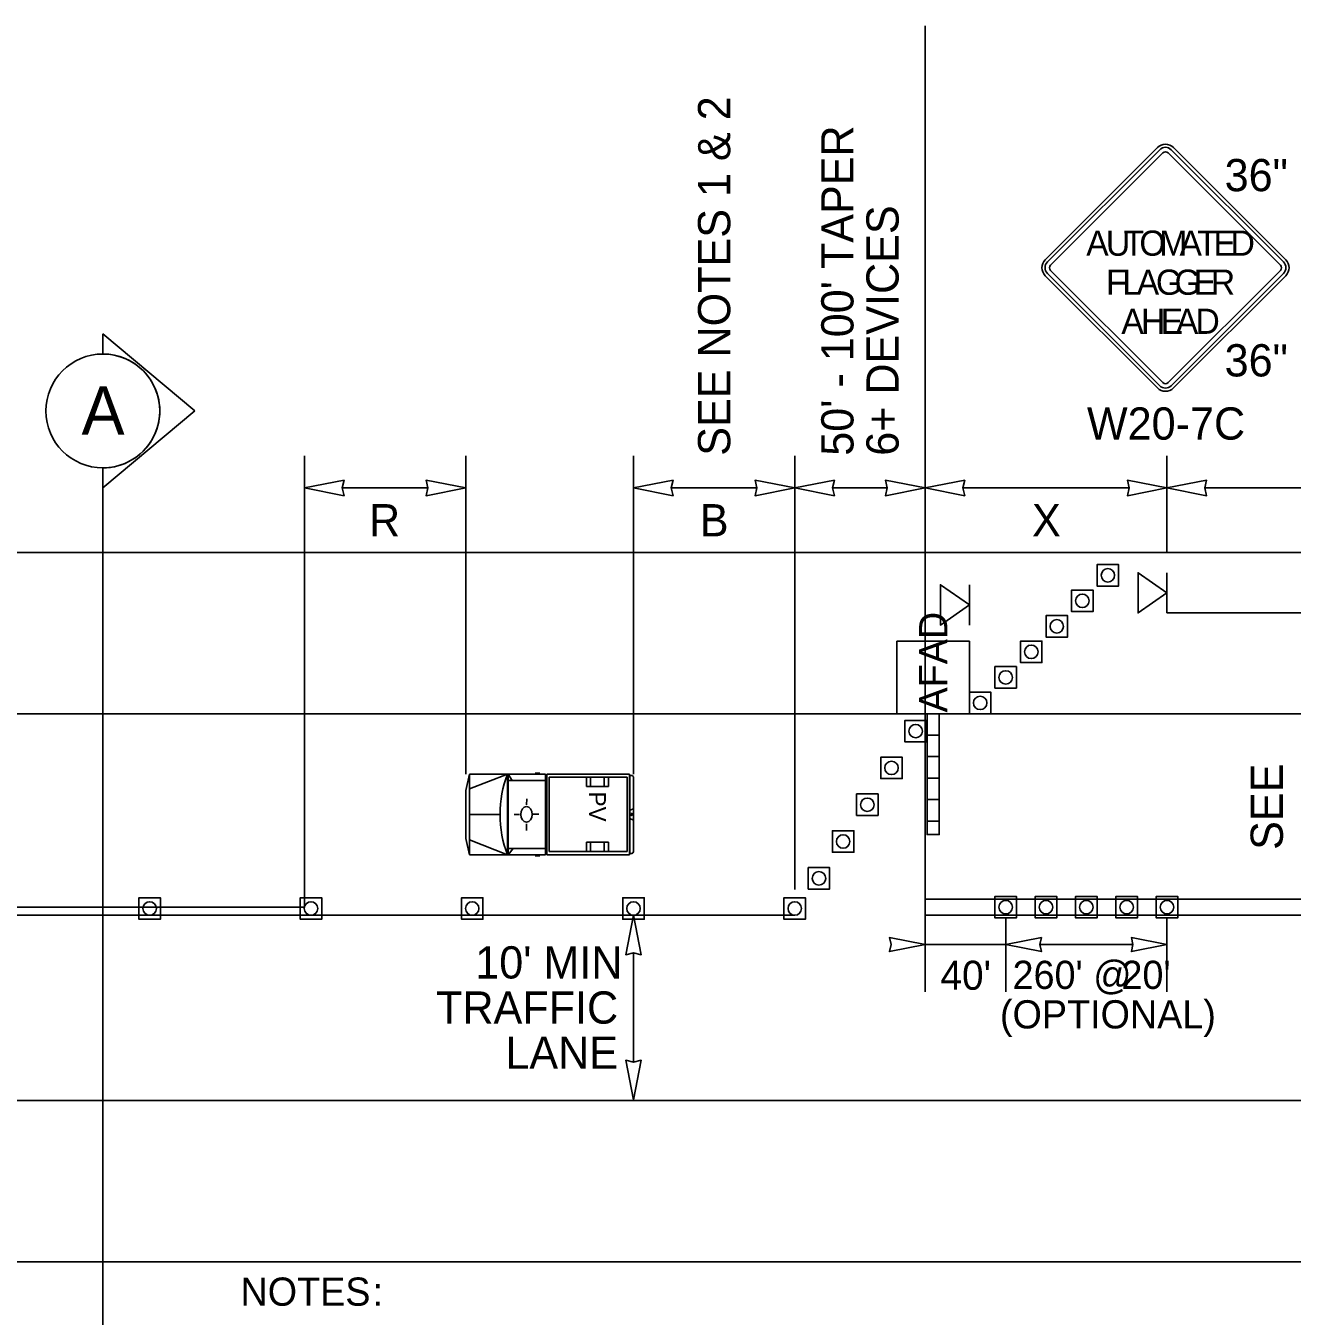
# Model space of a CAD drawing. Extents: x 99999.1 to 100095.7, y 99995 to 100010.7.
# Drawn here: x 100009.243 to 100012.384, y 100005.597 to 100008.799 of the extents above; entities that cross this region are included whole.
import ezdxf

# ---------------------------------------------------------------- set-up
doc = ezdxf.new("R2010")
doc.units = 0
for name, color, linetype in [('RD_ED_ShoulderPavedEdge', 7, 'Continuous'), ('RD_MK_LineDblYellowCenter', 7, 'Continuous'), ('RD_MK_LineEdgeWhite', 7, 'Continuous'), ('RD_MK_LineNoPass', 7, 'Continuous'), ('RD_MK_LineSkipCenter', 7, 'Continuous'), ('SH_GI_GeneralNotesBodyText', 7, 'Continuous'), ('SH_TI_WZSectionCut', 7, 'Continuous'), ('TR_SN_ConstructionSigns', 7, 'Continuous'), ('TR_WZ_AFAD', 7, 'Continuous'), ('TR_WZ_PortableSignMountBlk-Org', 7, 'Continuous'), ('TR_WZ_PortableSignMountBlk-Wht', 7, 'Continuous'), ('TR_WZ_ProtectiveVehicle', 7, 'Continuous'), ('TR_WZ_TrafficCone', 7, 'Continuous'), ('TR_WZ_WorkZoneDetails', 7, 'Continuous'), ('TR_WZ_WorkZoneTextCurrent', 7, 'Continuous')]:
    doc.layers.add(name, color=color, linetype=linetype)

msp = doc.modelspace()

# ---------------------------------------------------------------- linework, layer by layer
at = {"layer": 'RD_ED_ShoulderPavedEdge'}
for p, q in [((100000.1076, 100007.4923), (100015.6424, 100007.4923)), ((100000.1076, 100005.7323), (100015.6424, 100005.7323))]:
    msp.add_line(p, q, dxfattribs=at)
at = {"layer": 'RD_MK_LineDblYellowCenter'}
for p, q in [((100012.2733, 100006.6323), (100015.6631, 100006.6323)), ((100012.2733, 100006.5923), (100015.6218, 100006.5923))]:
    msp.add_line(p, q, dxfattribs=at)
at = {"layer": 'RD_MK_LineEdgeWhite'}
for p, q in [((100000.1076, 100007.0923), (100015.6424, 100007.0923)), ((100000.1076, 100006.1323), (100015.6424, 100006.1323))]:
    msp.add_line(p, q, dxfattribs=at)
at = {"layer": 'RD_MK_LineNoPass'}
msp.add_line((100011.4733, 100006.5923), (100012.2733, 100006.5923), dxfattribs=at)
at = {"layer": 'RD_MK_LineSkipCenter'}
for points in [[(100012.2733, 100006.6323), (100011.4733, 100006.6323)], [(100011.15, 100006.5923), (100003.4767, 100006.5923)]]:
    msp.add_lwpolyline(points, dxfattribs=at)
at = {"layer": 'SH_TI_WZSectionCut'}
for p, q in [((100009.4337, 100007.9847), (100009.4337, 100008.0346)), ((100009.4337, 100008.0346), (100009.6619, 100007.8435)), ((100009.6619, 100007.8435), (100009.4337, 100007.6523)), ((100009.4337, 100007.6523), (100009.4337, 100007.7022)), ((100009.4338, 100007.7022), (100009.4338, 100005.5723))]:
    msp.add_line(p, q, dxfattribs=at)
msp.add_circle((100009.4338, 100007.8435), 0.1412, dxfattribs=at)
msp.add_arc((100009.4338, 100007.8435), 0.1412, 269.9978, 90.0022, dxfattribs=at)
at = {"layer": 'TR_SN_ConstructionSigns'}
for p, q in [((100012.0497, 100008.4972), (100011.7713, 100008.2188)), ((100012.0552, 100008.4917), (100011.7768, 100008.2132)), ((100012.3624, 100008.2132), (100012.0839, 100008.4917)), ((100012.3679, 100008.2188), (100012.0895, 100008.4972)), ((100011.7845, 100008.2055), (100012.063, 100008.4839)), ((100012.0762, 100008.4839), (100012.3546, 100008.2055)), ((100011.7713, 100008.179), (100012.0497, 100007.9006)), ((100011.7768, 100008.1845), (100012.0552, 100007.9061)), ((100012.063, 100007.9138), (100011.7845, 100008.1923)), ((100012.3546, 100008.1923), (100012.0762, 100007.9138)), ((100012.0839, 100007.9061), (100012.3624, 100008.1845)), ((100012.0895, 100007.9006), (100012.3679, 100008.179))]:
    msp.add_line(p, q, dxfattribs=at)
for centre, radius, start, end in [((100012.0696, 100008.4773), 0.0281, 45, 135), ((100012.0696, 100008.4773), 0.0203, 45, 135), ((100012.0696, 100008.4773), 0.00937, 45, 135), ((100011.7912, 100008.1989), 0.0281, 135, 225), ((100011.7912, 100008.1989), 0.0203, 135, 225), ((100011.7912, 100008.1989), 0.00937, 135, 225), ((100012.348, 100008.1989), 0.00937, 315, 45), ((100012.348, 100008.1989), 0.0203, 315, 45), ((100012.348, 100008.1989), 0.0281, 315, 45), ((100012.0696, 100007.9205), 0.00937, 225, 315), ((100012.0696, 100007.9205), 0.0281, 225, 315), ((100012.0696, 100007.9205), 0.0203, 225, 315)]:
    msp.add_arc(centre, radius, start, end, dxfattribs=at)
at = {"layer": 'TR_WZ_AFAD'}
for p, q in [((100011.4033, 100007.0923), (100011.4033, 100007.2723)), ((100011.4033, 100007.2723), (100011.5833, 100007.2723)), ((100011.5833, 100007.2723), (100011.4033, 100007.2723)), ((100011.4033, 100007.2723), (100011.4033, 100007.0923)), ((100011.5833, 100007.2723), (100011.5833, 100007.0923)), ((100011.5833, 100007.0923), (100011.5833, 100007.2723)), ((100011.5833, 100007.0923), (100011.4033, 100007.0923)), ((100011.5, 100007.0923), (100011.4933, 100007.0923)), ((100011.5, 100007.0923), (100011.5833, 100007.0923)), ((100011.5083, 100007.0923), (100011.5, 100007.0923)), ((100011.5083, 100007.039), (100011.5083, 100007.0923)), ((100011.4783, 100007.039), (100011.4783, 100006.9857)), ((100011.5083, 100006.9857), (100011.5083, 100007.039)), ((100011.4783, 100006.9857), (100011.4783, 100006.9323)), ((100011.4783, 100006.9857), (100011.4933, 100006.9857)), ((100011.4933, 100006.9857), (100011.5083, 100006.9857)), ((100011.5083, 100006.9323), (100011.5083, 100006.9857)), ((100011.4933, 100006.9323), (100011.4783, 100006.9323)), ((100011.4783, 100006.9323), (100011.4783, 100006.879)), ((100011.5083, 100006.9323), (100011.4933, 100006.9323)), ((100011.5083, 100006.879), (100011.5083, 100006.9323)), ((100011.4783, 100006.879), (100011.4783, 100006.8257)), ((100011.4783, 100006.879), (100011.4933, 100006.879)), ((100011.4933, 100006.879), (100011.5083, 100006.879)), ((100011.5083, 100006.8257), (100011.5083, 100006.879)), ((100011.4933, 100006.8257), (100011.4783, 100006.8257)), ((100011.4783, 100006.8257), (100011.4783, 100006.7923)), ((100011.5083, 100006.8257), (100011.4933, 100006.8257))]:
    msp.add_line(p, q, dxfattribs=at)
for points in [[(100011.4033, 100007.0923), (100011.4867, 100007.0923), (100011.5, 100007.0923)], [(100011.4933, 100007.0923), (100011.4867, 100007.0923), (100011.4783, 100007.0923), (100011.4783, 100007.039)], [(100011.4783, 100007.0923), (100011.4783, 100006.7923), (100011.5083, 100006.7923), (100011.5083, 100007.0923)], [(100011.4783, 100007.039), (100011.4933, 100007.039), (100011.5083, 100007.039)], [(100011.5083, 100007.039), (100011.4933, 100007.039), (100011.4783, 100007.039)], [(100011.5083, 100006.9857), (100011.4933, 100006.9857), (100011.4783, 100006.9857)], [(100011.4783, 100006.9323), (100011.4933, 100006.9323), (100011.5083, 100006.9323)], [(100011.5083, 100006.879), (100011.4933, 100006.879), (100011.4783, 100006.879)], [(100011.4783, 100006.8257), (100011.4933, 100006.8257), (100011.5083, 100006.8257)], [(100011.4783, 100006.7923), (100011.5083, 100006.7923), (100011.5083, 100006.8257)]]:
    msp.add_lwpolyline(points, dxfattribs=at)
at = {"layer": 'TR_WZ_PortableSignMountBlk-Org'}
msp.add_line((100012.0733, 100007.4422), (100012.0733, 100007.3422), dxfattribs=at)
msp.add_lwpolyline([(100012.0733, 100007.3923), (100012.0015, 100007.3422), (100012.0015, 100007.4422)], close=True, dxfattribs=at)
at = {"layer": 'TR_WZ_PortableSignMountBlk-Wht'}
msp.add_line((100011.5833, 100007.4123), (100011.5833, 100007.3123), dxfattribs=at)
msp.add_lwpolyline([(100011.5833, 100007.3624), (100011.5115, 100007.3123), (100011.5115, 100007.4123)], close=True, dxfattribs=at)
at = {"layer": 'TR_WZ_ProtectiveVehicle'}
for p, q in [((100010.343, 100006.9423), (100010.3338, 100006.902)), ((100010.343, 100006.7423), (100010.343, 100006.9423)), ((100010.343, 100006.9423), (100010.5319, 100006.9423)), ((100010.343, 100006.9057), (100010.4375, 100006.9423)), ((100010.4375, 100006.7423), (100010.4375, 100006.9423)), ((100010.4392, 100006.7423), (100010.4392, 100006.9423)), ((100010.4492, 100006.9268), (100010.4392, 100006.9423)), ((100010.4392, 100006.9268), (100010.5319, 100006.9268)), ((100010.5062, 100006.9451), (100010.5175, 100006.9451)), ((100010.5319, 100006.7423), (100010.5319, 100006.9423)), ((100010.7404, 100006.9423), (100010.5347, 100006.9423)), ((100010.5347, 100006.7423), (100010.5347, 100006.9423)), ((100010.7346, 100006.9344), (100010.5405, 100006.9344)), ((100010.5405, 100006.7503), (100010.5405, 100006.9344)), ((100010.6332, 100006.9344), (100010.6332, 100006.9113)), ((100010.6432, 100006.9344), (100010.6432, 100006.9113)), ((100010.6772, 100006.9344), (100010.6772, 100006.9113)), ((100010.6882, 100006.9344), (100010.6882, 100006.9113)), ((100010.7346, 100006.7503), (100010.7346, 100006.9344)), ((100010.7404, 100006.7423), (100010.7404, 100006.9423)), ((100010.7456, 100006.939), (100010.7411, 100006.939)), ((100010.7411, 100006.7456), (100010.7411, 100006.939)), ((100010.75, 100006.7517), (100010.75, 100006.9329)), ((100010.3338, 100006.7827), (100010.3338, 100006.902)), ((100010.6882, 100006.9113), (100010.6332, 100006.9113)), ((100010.4852, 100006.8808), (100010.485, 100006.8658)), ((100010.75, 100006.8564), (100010.7411, 100006.8527)), ((100010.343, 100006.8423), (100010.4189, 100006.8423)), ((100010.4544, 100006.8422), (100010.467, 100006.8423)), ((100010.4986, 100006.8427), (100010.4986, 100006.8427)), ((100010.5154, 100006.8431), (100010.5005, 100006.8427)), ((100010.75, 100006.8282), (100010.7411, 100006.832)), ((100010.7476, 100006.8423), (100010.7435, 100006.8423)), ((100010.7456, 100006.8395), (100010.7456, 100006.8451)), ((100010.4845, 100006.8027), (100010.4845, 100006.8188)), ((100010.343, 100006.7423), (100010.3338, 100006.7827)), ((100010.343, 100006.779), (100010.4375, 100006.7423)), ((100010.4392, 100006.7423), (100010.4512, 100006.7578)), ((100010.4392, 100006.7578), (100010.5319, 100006.7578)), ((100010.6882, 100006.7733), (100010.6332, 100006.7733)), ((100010.6332, 100006.7503), (100010.6332, 100006.7733)), ((100010.6432, 100006.7503), (100010.6432, 100006.7733)), ((100010.6772, 100006.7503), (100010.6772, 100006.7733)), ((100010.6882, 100006.7503), (100010.6882, 100006.7733)), ((100010.343, 100006.7423), (100010.5319, 100006.7423)), ((100010.5062, 100006.7395), (100010.5175, 100006.7395)), ((100010.7404, 100006.7423), (100010.5347, 100006.7423)), ((100010.7346, 100006.7503), (100010.5405, 100006.7503)), ((100010.7456, 100006.7456), (100010.7411, 100006.7456))]:
    msp.add_line(p, q, dxfattribs=at)
for centre, major_axis, start_param, end_param in [((100010.5725, 100006.8424), (0, -0.2099), 4.215852, 5.209111), ((100010.7456, 100006.9329), (0, 0.0061), 4.712389, 6.283185), ((100010.7456, 100006.7517), (0, -0.0061), 6.283185, 7.853982)]:
    msp.add_ellipse(centre, major_axis=major_axis, ratio=0.73155, start_param=start_param, end_param=end_param, dxfattribs=at)
for centre, major_axis in [((100010.4845, 100006.8423), (0, 0.0193)), ((100010.7456, 100006.8423), (0, 0.00282))]:
    msp.add_ellipse(centre, major_axis=major_axis, ratio=0.73155, dxfattribs=at)
at = {"layer": 'TR_WZ_TrafficCone'}
for points in [[(100011.9533, 100007.4623), (100011.9, 100007.4623), (100011.9, 100007.409), (100011.9533, 100007.409), (100011.9533, 100007.4623)], [(100011.9533, 100007.409), (100011.9, 100007.409), (100011.9, 100007.4623), (100011.9533, 100007.4623), (100011.9533, 100007.409)], [(100011.89, 100007.399), (100011.8367, 100007.399), (100011.8367, 100007.3457), (100011.89, 100007.3457), (100011.89, 100007.399)], [(100011.89, 100007.3457), (100011.8367, 100007.3457), (100011.8367, 100007.399), (100011.89, 100007.399), (100011.89, 100007.3457)], [(100011.8267, 100007.3357), (100011.7733, 100007.3357), (100011.7733, 100007.2823), (100011.8267, 100007.2823), (100011.8267, 100007.3357)], [(100011.8267, 100007.2823), (100011.7733, 100007.2823), (100011.7733, 100007.3357), (100011.8267, 100007.3357), (100011.8267, 100007.2823)], [(100011.7633, 100007.219), (100011.71, 100007.219), (100011.71, 100007.2723), (100011.7633, 100007.2723), (100011.7633, 100007.219)], [(100011.7633, 100007.2723), (100011.71, 100007.2723), (100011.71, 100007.219), (100011.7633, 100007.219), (100011.7633, 100007.2723)], [(100011.7, 100007.1557), (100011.6467, 100007.1557), (100011.6467, 100007.209), (100011.7, 100007.209), (100011.7, 100007.1557)], [(100011.7, 100007.209), (100011.6467, 100007.209), (100011.6467, 100007.1557), (100011.7, 100007.1557), (100011.7, 100007.209)], [(100011.6367, 100007.0923), (100011.5833, 100007.0923), (100011.5833, 100007.1457), (100011.6367, 100007.1457), (100011.6367, 100007.0923)], [(100011.6367, 100007.1457), (100011.5833, 100007.1457), (100011.5833, 100007.0923), (100011.6367, 100007.0923), (100011.6367, 100007.1457)], [(100011.4766, 100007.0757), (100011.4233, 100007.0757), (100011.4233, 100007.0224), (100011.4766, 100007.0224), (100011.4766, 100007.0757)], [(100011.4766, 100007.0224), (100011.4233, 100007.0224), (100011.4233, 100007.0757), (100011.4766, 100007.0757), (100011.4766, 100007.0224)], [(100011.4166, 100006.9844), (100011.3633, 100006.9844), (100011.3633, 100006.9311), (100011.4166, 100006.9311), (100011.4166, 100006.9844)], [(100011.4166, 100006.9311), (100011.3633, 100006.9311), (100011.3633, 100006.9844), (100011.4166, 100006.9844), (100011.4166, 100006.9311)], [(100011.3566, 100006.8931), (100011.3033, 100006.8931), (100011.3033, 100006.8397), (100011.3566, 100006.8397), (100011.3566, 100006.8931)], [(100011.3566, 100006.8397), (100011.3033, 100006.8397), (100011.3033, 100006.8931), (100011.3566, 100006.8931), (100011.3566, 100006.8397)], [(100011.2966, 100006.8017), (100011.2433, 100006.8017), (100011.2433, 100006.7484), (100011.2966, 100006.7484), (100011.2966, 100006.8017)], [(100011.2966, 100006.7484), (100011.2433, 100006.7484), (100011.2433, 100006.8017), (100011.2966, 100006.8017), (100011.2966, 100006.7484)], [(100011.2366, 100006.7104), (100011.1833, 100006.7104), (100011.1833, 100006.6571), (100011.2366, 100006.6571), (100011.2366, 100006.7104)], [(100011.2366, 100006.6571), (100011.1833, 100006.6571), (100011.1833, 100006.7104), (100011.2366, 100006.7104), (100011.2366, 100006.6571)], [(100009.5234, 100006.6357), (100009.5767, 100006.6357), (100009.5767, 100006.5823), (100009.5234, 100006.5823), (100009.5234, 100006.6357)], [(100009.5234, 100006.5823), (100009.5767, 100006.5823), (100009.5767, 100006.6357), (100009.5234, 100006.6357), (100009.5234, 100006.5823)], [(100009.9234, 100006.6357), (100009.9767, 100006.6357), (100009.9767, 100006.5823), (100009.9234, 100006.5823), (100009.9234, 100006.6357)], [(100009.9234, 100006.5823), (100009.9767, 100006.5823), (100009.9767, 100006.6357), (100009.9234, 100006.6357), (100009.9234, 100006.5823)], [(100010.3234, 100006.6357), (100010.3767, 100006.6357), (100010.3767, 100006.5823), (100010.3234, 100006.5823), (100010.3234, 100006.6357)], [(100010.3234, 100006.5823), (100010.3767, 100006.5823), (100010.3767, 100006.6357), (100010.3234, 100006.6357), (100010.3234, 100006.5823)], [(100010.7234, 100006.6357), (100010.7767, 100006.6357), (100010.7767, 100006.5823), (100010.7234, 100006.5823), (100010.7234, 100006.6357)], [(100010.7234, 100006.5823), (100010.7767, 100006.5823), (100010.7767, 100006.6357), (100010.7234, 100006.6357), (100010.7234, 100006.5823)], [(100011.1766, 100006.6357), (100011.1233, 100006.6357), (100011.1233, 100006.5823), (100011.1766, 100006.5823), (100011.1766, 100006.6357)], [(100011.1766, 100006.5823), (100011.1233, 100006.5823), (100011.1233, 100006.6357), (100011.1766, 100006.6357), (100011.1766, 100006.5823)], [(100011.7, 100006.639), (100011.6467, 100006.639), (100011.6467, 100006.5857), (100011.7, 100006.5857), (100011.7, 100006.639)], [(100011.7, 100006.5857), (100011.6467, 100006.5857), (100011.6467, 100006.639), (100011.7, 100006.639), (100011.7, 100006.5857)], [(100011.8, 100006.639), (100011.7467, 100006.639), (100011.7467, 100006.5857), (100011.8, 100006.5857), (100011.8, 100006.639)], [(100011.8, 100006.5857), (100011.7467, 100006.5857), (100011.7467, 100006.639), (100011.8, 100006.639), (100011.8, 100006.5857)], [(100011.9, 100006.639), (100011.8467, 100006.639), (100011.8467, 100006.5857), (100011.9, 100006.5857), (100011.9, 100006.639)], [(100011.9, 100006.5857), (100011.8467, 100006.5857), (100011.8467, 100006.639), (100011.9, 100006.639), (100011.9, 100006.5857)], [(100012, 100006.639), (100011.9467, 100006.639), (100011.9467, 100006.5857), (100012, 100006.5857), (100012, 100006.639)], [(100012, 100006.5857), (100011.9467, 100006.5857), (100011.9467, 100006.639), (100012, 100006.639), (100012, 100006.5857)], [(100012.1, 100006.639), (100012.0467, 100006.639), (100012.0467, 100006.5857), (100012.1, 100006.5857), (100012.1, 100006.639)], [(100012.1, 100006.5857), (100012.0467, 100006.5857), (100012.0467, 100006.639), (100012.1, 100006.639), (100012.1, 100006.5857)]]:
    msp.add_lwpolyline(points, dxfattribs=at)
for centre in [(100011.9267, 100007.4357), (100011.8633, 100007.3723), (100011.8, 100007.309), (100011.7367, 100007.2457), (100011.6733, 100007.1823), (100011.61, 100007.119), (100011.45, 100007.0491), (100011.39, 100006.9577), (100011.33, 100006.8664), (100011.27, 100006.7751), (100011.21, 100006.6837), (100009.55, 100006.609), (100009.95, 100006.609), (100010.35, 100006.609), (100010.75, 100006.609), (100011.15, 100006.609), (100011.6733, 100006.6123), (100011.7733, 100006.6123), (100011.8733, 100006.6123), (100011.9733, 100006.6123), (100012.0733, 100006.6123)]:
    msp.add_circle(centre, 0.0167, dxfattribs=at)
at = {"layer": 'TR_WZ_WorkZoneDetails'}
for p, q in [((100011.4733, 100007.0923), (100011.4733, 100008.7991)), ((100009.9338, 100007.4923), (100009.9338, 100007.7323)), ((100010.3338, 100006.9423), (100010.3338, 100007.7323)), ((100010.75, 100006.9423), (100010.75, 100007.7323)), ((100011.15, 100006.6557), (100011.15, 100007.7323)), ((100012.0733, 100007.4923), (100012.0733, 100007.7323)), ((100010.24, 100007.6523), (100010.0275, 100007.6523)), ((100011.0563, 100007.6523), (100010.8437, 100007.6523)), ((100011.3796, 100007.6523), (100011.2437, 100007.6523)), ((100011.5671, 100007.6523), (100011.9796, 100007.6523)), ((100012.1671, 100007.6523), (100012.7296, 100007.6523)), ((100012.0733, 100007.3422), (100015.1733, 100007.3422)), ((100011.4733, 100007.0923), (100011.4733, 100006.4023)), ((100011.6733, 100006.5857), (100011.6733, 100006.4023)), ((100012.0733, 100006.5857), (100012.0733, 100006.4023)), ((100011.6733, 100006.5193), (100011.4733, 100006.5193)), ((100011.989, 100006.5193), (100011.7577, 100006.5193)), ((100010.75, 100006.2278), (100010.75, 100006.4986))]:
    msp.add_line(p, q, dxfattribs=at)
for points in [[(100009.9338, 100007.6523), (100010.032, 100007.6331), (100010.0275, 100007.6523), (100010.032, 100007.6716)], [(100010.3338, 100007.6523), (100010.2355, 100007.6331), (100010.24, 100007.6523), (100010.2355, 100007.6716)], [(100010.75, 100007.6523), (100010.8483, 100007.6331), (100010.8437, 100007.6523), (100010.8483, 100007.6716)], [(100011.15, 100007.6523), (100011.0517, 100007.6331), (100011.0563, 100007.6523), (100011.0517, 100007.6716)], [(100011.15, 100007.6523), (100011.2483, 100007.6331), (100011.2437, 100007.6523), (100011.2483, 100007.6716)], [(100011.4733, 100007.6523), (100011.3751, 100007.6331), (100011.3796, 100007.6523), (100011.3751, 100007.6716)], [(100011.4733, 100007.6523), (100011.5716, 100007.6331), (100011.5671, 100007.6523), (100011.5716, 100007.6716)], [(100012.0733, 100007.6523), (100011.9751, 100007.6331), (100011.9796, 100007.6523), (100011.9751, 100007.6716)], [(100012.0733, 100007.6523), (100012.1716, 100007.6331), (100012.1671, 100007.6523), (100012.1716, 100007.6716)], [(100005.15, 100007.4923), (100005.15, 100006.6123), (100009.9338, 100006.6123), (100009.9338, 100007.4923)], [(100010.75, 100006.5923), (100010.7307, 100006.4941), (100010.75, 100006.4986), (100010.7692, 100006.4941)], [(100011.4733, 100006.5193), (100011.3849, 100006.502), (100011.389, 100006.5193), (100011.3849, 100006.5367)], [(100011.6733, 100006.5193), (100011.7618, 100006.502), (100011.7577, 100006.5193), (100011.7618, 100006.5367)], [(100012.0733, 100006.5193), (100011.9849, 100006.502), (100011.989, 100006.5193), (100011.9849, 100006.5367)], [(100010.75, 100006.1341), (100010.7307, 100006.2324), (100010.75, 100006.2278), (100010.7692, 100006.2324)]]:
    msp.add_lwpolyline(points, close=True, dxfattribs=at)

# ---------------------------------------------------------------- texts
at = {"layer": 'SH_GI_GeneralNotesBodyText'}
for s, p in [('NOTES', (100009.7751, 100005.6233)), (':', (100010.1026, 100005.6233))]:
    msp.add_text(s, height=0.07, rotation=360, dxfattribs=at).set_placement(p)
at = {"layer": 'SH_TI_WZSectionCut'}
msp.add_text('A', height=0.12, rotation=359.99, dxfattribs=at).set_placement((100009.3808, 100007.7843))
at = {"layer": 'TR_SN_ConstructionSigns'}
for s, p in [('36"', (100012.2163, 100008.3887)), ('36"', (100012.2163, 100007.9291)), ('W20-7C', (100011.8748, 100007.7723))]:
    msp.add_text(s, height=0.08, rotation=360, dxfattribs=at).set_placement(p)
for s, p in [('A', (100011.873, 100008.2286)), ('U', (100011.9218, 100008.2286)), ('T', (100011.9655, 100008.2286)), ('O', (100012.0049, 100008.2286)), ('M', (100012.0543, 100008.2286)), ('A', (100012.1043, 100008.2286)), ('T', (100012.148, 100008.2286)), ('E', (100012.1886, 100008.2286)), ('D', (100012.2311, 100008.2286)), ('F', (100011.9221, 100008.1317)), ('L', (100011.9627, 100008.1317)), ('A', (100011.9983, 100008.1317)), ('G', (100012.0458, 100008.1317)), ('G', (100012.0921, 100008.1317)), ('E', (100012.1396, 100008.1317)), ('R', (100012.1821, 100008.1317)), ('A', (100011.9602, 100008.0348)), ('H', (100012.009, 100008.0348)), ('E', (100012.0577, 100008.0348)), ('A', (100012.0952, 100008.0348)), ('D', (100012.144, 100008.0348))]:
    msp.add_text(s, height=0.0625, dxfattribs=at).set_placement(p)
at = {"layer": 'TR_WZ_AFAD'}
msp.add_text('AFAD', height=0.07, rotation=90, dxfattribs=at).set_placement((100011.5283, 100007.0953))
at = {"layer": 'TR_WZ_ProtectiveVehicle'}
msp.add_text('PV', height=0.04175, rotation=270, dxfattribs=at).set_placement((100010.6398, 100006.899))
at = {"layer": 'TR_WZ_WorkZoneDetails'}
msp.add_text('SEE', height=0.08, rotation=90, dxfattribs=at).set_placement((100012.3608, 100006.7544))
at = {"layer": 'TR_WZ_WorkZoneTextCurrent'}
for s, p in [('SEE NOTES 1 & 2', (100010.99, 100007.7323)), ("50' - 100' TAPER", (100011.2957, 100007.7323)), ('6+ DEVICES', (100011.4077, 100007.7323))]:
    msp.add_text(s, height=0.08, rotation=90, dxfattribs=at).set_placement(p)
for s, height, p in [('R', 0.08, (100010.0939, 100007.5323)), ('B', 0.08, (100010.9145, 100007.5323)), ('X', 0.08, (100011.7386, 100007.5323)), ("10' MIN", 0.08, (100010.3575, 100006.4352)), ("40'", 0.072, (100011.5114, 100006.4073)), ("260' @", 0.07, (100011.6903, 100006.4093)), ("20'", 0.07, (100011.9604, 100006.4093)), ('TRAFFIC', 0.08, (100010.2603, 100006.3232)), ('(OPTIONAL)', 0.07, (100011.659, 100006.3113)), ('LANE', 0.08, (100010.4322, 100006.2112))]:
    msp.add_text(s, height=height, dxfattribs=at).set_placement(p)

doc.saveas('drawing.dxf')
